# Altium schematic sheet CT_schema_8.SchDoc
size 278 x 170 mm
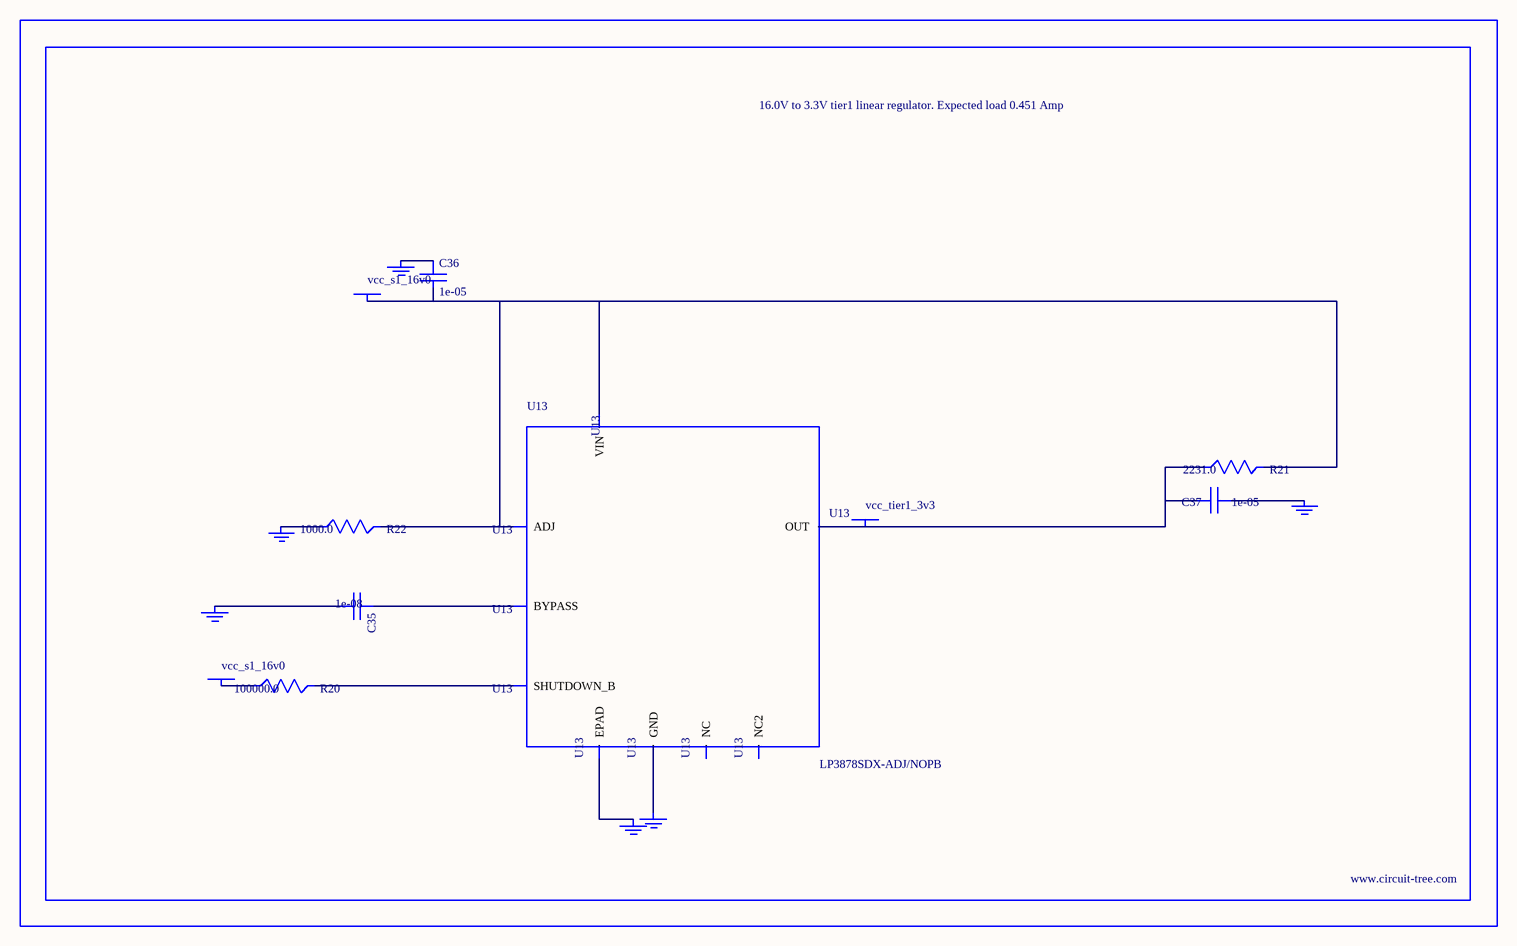
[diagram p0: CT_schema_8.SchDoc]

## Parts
BORDER7  (no value)
C35  1e-08  [C0402]
C36  1e-05  [C1210]
C37  1e-05  [C1210]
GND_INSTANCE_7_0  (no value)
GND_INSTANCE_7_1  (no value)
GND_INSTANCE_7_2  (no value)
GND_INSTANCE_7_3  (no value)
GND_INSTANCE_7_4  (no value)
GND_INSTANCE_7_5  (no value)
POWER_INSTANCE_7_0  vcc_s1_16v0
POWER_INSTANCE_7_1  vcc_s1_16v0
POWER_INSTANCE_7_2  vcc_tier1_3v3
R20  100000.0  [R0603]
R21  2231.0  [R0603]
R22  1000.0  [R0603]
U13  LP3878SDX-ADJ/NOPB  [WSON-8]

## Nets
NetC35_1: C35.1 U13.1(BYPASS)
NetC35_2: C35.2 GND_INSTANCE_7_0.0(GND)
NetC36_1: C36.1 GND_INSTANCE_7_1.0(GND)
NetC36_2: C36.2 POWER_INSTANCE_7_0.0(PWR) R21.2 R22.2 U13.4(VIN) U13.6(ADJ)
NetC37_1: C37.1 GND_INSTANCE_7_2.0(GND)
NetC37_2: C37.2 POWER_INSTANCE_7_2.0(PWR) R21.1 U13.5(OUT)
NetGND_INSTANCE_7_3_0: GND_INSTANCE_7_3.0(GND) R22.1
NetGND_INSTANCE_7_4_0: GND_INSTANCE_7_4.0(GND) U13.PAD(EPAD)
NetGND_INSTANCE_7_5_0: GND_INSTANCE_7_5.0(GND) U13.3(GND)
NetPOWER_INSTANCE_7_1_0: POWER_INSTANCE_7_1.0(PWR) R20.1
NetR20_2: R20.2 U13.8(SHUTDOWN_B)

Not connected (* = marked no-connect by the designer): U13 2(NC) 7(NC2)

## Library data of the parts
BORDER7 = BORDER_PAGE7
C35 = C0402C103K3RAC
C36 = C1210C106K5PACTU
C37 = GRM32DR61E106MA12L
GND_INSTANCE_7_0-GND_INSTANCE_7_5 = GND
POWER_INSTANCE_7_0-POWER_INSTANCE_7_2 = PWR
R20 = RC0603JR-07100KL
R21 = R21
R22 = RC0603JR-071KL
